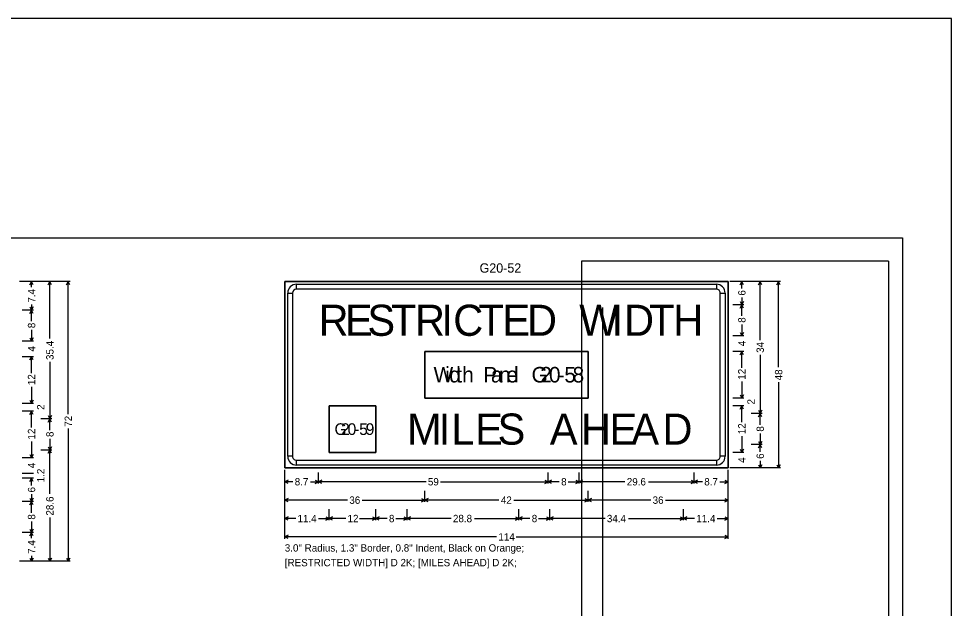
# Model space of a CAD drawing. Extents: x -1403959 to 81668, y -1400582 to 11018.
# Drawn here: x -1402613 to -1400615, y -1399262 to -1397998 of the extents above; entities that cross this region are included whole.
import ezdxf

# ---------------------------------------------------------------- set-up
doc = ezdxf.new("R2010")
doc.units = 0
for name, color, linetype in [('tdCiInt', 7, 'Continuous'), ('tdCiIntRampCL', 7, 'Continuous'), ('tdCiPriRamp', 7, 'Continuous'), ('tdCiPriRampCL', 7, 'Continuous'), ('tdRailNorfolk_South', 7, 'Continuous'), ('trf_Sign_Details_Border', 7, 'Continuous'), ('trf_Sign_Details_Dimensions', 7, 'Continuous')]:
    doc.layers.add(name, color=color, linetype=linetype)

msp = doc.modelspace()

# ---------------------------------------------------------------- linework, layer by layer
at = {"layer": 'tdCiInt'}
for p, q in [((-1402018.1, -1398577.7), (-1402018.1, -1398567.3)), ((-1401118.1, -1398567.3), (-1401118.1, -1398577.7)), ((-1402036.8, -1398586), (-1402026.4, -1398586)), ((-1401109.7, -1398586), (-1401099.3, -1398586)), ((-1401393.1, -1398711), (-1401743.1, -1398711)), ((-1401743.1, -1398711), (-1401743.1, -1398811)), ((-1401393.1, -1398811), (-1401393.1, -1398711)), ((-1401743.1, -1398811), (-1401393.1, -1398811)), ((-1401847.7, -1398827.7), (-1401947.7, -1398827.7)), ((-1401947.7, -1398827.7), (-1401947.7, -1398927.7)), ((-1401847.7, -1398927.7), (-1401847.7, -1398827.7)), ((-1402026.4, -1398936), (-1402036.8, -1398936)), ((-1401947.7, -1398927.7), (-1401847.7, -1398927.7)), ((-1401099.3, -1398936), (-1401109.7, -1398936)), ((-1402018.1, -1398954.8), (-1402018.1, -1398944.4)), ((-1401118.1, -1398944.4), (-1401118.1, -1398954.8))]:
    msp.add_line(p, q, dxfattribs=at)
for points in [[(-1402043.1, -1398961), (-1401093.1, -1398961), (-1401093.1, -1398561), (-1402043.1, -1398561), (-1402043.1, -1398961)], [(-1401118.1, -1398577.7), (-1402018.1, -1398577.7), (-1402018.1, -1398567.3), (-1401118.1, -1398567.3), (-1401118.1, -1398577.7)], [(-1402026.4, -1398586), (-1402026.4, -1398936), (-1402036.8, -1398936), (-1402036.8, -1398586), (-1402026.4, -1398586)], [(-1401109.7, -1398936), (-1401109.7, -1398586), (-1401099.3, -1398586), (-1401099.3, -1398936), (-1401109.7, -1398936)], [(-1402018.1, -1398944.4), (-1401118.1, -1398944.4), (-1401118.1, -1398954.8), (-1402018.1, -1398954.8), (-1402018.1, -1398944.4)]]:
    msp.add_lwpolyline(points, close=True, dxfattribs=at)
for centre, radius, start, end in [((-1402018.1, -1398586), 18.8, 90.0002, 179.9998), ((-1402018.1, -1398586), 8.33, 90.0002, 179.9998), ((-1401118.1, -1398586), 18.8, 0, 90.0002), ((-1401118.1, -1398586), 8.33, 0, 90.0002), ((-1402018.1, -1398936), 18.8, 179.9998, 270.0001), ((-1402018.1, -1398936), 8.33, 179.9998, 270.0001), ((-1401118.1, -1398936), 18.8, 270.0001, 0.0003), ((-1401118.1, -1398936), 8.33, 270.0001, 0.0003)]:
    msp.add_arc(centre, radius, start, end, dxfattribs=at)
at = {"layer": 'tdCiIntRampCL'}
msp.add_lwpolyline([(-1403958.5, -1400581.8), (-1400614.5, -1400581.8), (-1400614.5, -1397997.8), (-1403958.5, -1397997.8)], close=True, dxfattribs=at)
at = {"layer": 'tdCiPriRamp'}
msp.add_lwpolyline([(-1403854, -1398467.3), (-1400719, -1398467.3), (-1400719, -1400477.3), (-1403854, -1400477.3)], close=True, dxfattribs=at)
at = {"layer": 'tdCiPriRampCL'}
for p, q in [((-1401407.1, -1398517.3), (-1401407.1, -1399987.3)), ((-1400749, -1398517.3), (-1401407.1, -1398517.3)), ((-1400749, -1398517.3), (-1400749, -1399987.3)), ((-1401362.1, -1398617.3), (-1401362.1, -1399608.8))]:
    msp.add_line(p, q, dxfattribs=at)
at = {"layer": 'trf_Sign_Details_Border'}
for points in [[(-1402043.1, -1398561), (-1401093.1, -1398561), (-1401093.1, -1398961), (-1402043.1, -1398961)], [(-1401743.1, -1398711), (-1401393.1, -1398711), (-1401393.1, -1398811), (-1401743.1, -1398811)], [(-1401947.7, -1398827.7), (-1401847.7, -1398827.7), (-1401847.7, -1398927.7), (-1401947.7, -1398927.7)]]:
    msp.add_lwpolyline(points, close=True, dxfattribs=at)
at = {"layer": 'trf_Sign_Details_Dimensions'}
for p, q in [((-1402503.2, -1398561), (-1402611.5, -1398561)), ((-1402582, -1398561), (-1402605.6, -1398561)), ((-1402589.4, -1398568.1), (-1402585.9, -1398561)), ((-1402585.9, -1398573.1), (-1402585.9, -1398561)), ((-1402582.4, -1398568.1), (-1402585.9, -1398561)), ((-1402542.6, -1398561), (-1402566.2, -1398561)), ((-1402550.1, -1398568.1), (-1402546.5, -1398561)), ((-1402546.5, -1398683.4), (-1402546.5, -1398561)), ((-1402543, -1398568.1), (-1402546.5, -1398561)), ((-1402510.7, -1398568.1), (-1402507.2, -1398561)), ((-1402507.2, -1398845.5), (-1402507.2, -1398561)), ((-1402503.6, -1398568.1), (-1402507.2, -1398561)), ((-1400980.9, -1398561), (-1401089.1, -1398561)), ((-1401059.6, -1398561), (-1401083.2, -1398561)), ((-1401067.1, -1398568.1), (-1401063.5, -1398561)), ((-1401063.5, -1398576.6), (-1401063.5, -1398561)), ((-1401060, -1398568.1), (-1401063.5, -1398561)), ((-1401020.2, -1398561), (-1401043.9, -1398561)), ((-1401027.7, -1398568.1), (-1401024.2, -1398561)), ((-1401024.2, -1398687.2), (-1401024.2, -1398561)), ((-1401020.7, -1398568.1), (-1401024.2, -1398561)), ((-1400988.3, -1398568.1), (-1400984.8, -1398561)), ((-1400984.8, -1398745), (-1400984.8, -1398561)), ((-1400981.3, -1398568.1), (-1400984.8, -1398561)), ((-1401067.1, -1398604), (-1401063.5, -1398611)), ((-1401063.5, -1398595.5), (-1401063.5, -1398611)), ((-1401060, -1398604), (-1401063.5, -1398611)), ((-1402582, -1398622.5), (-1402605.6, -1398622.5)), ((-1402589.4, -1398615.4), (-1402585.9, -1398622.5)), ((-1402589.4, -1398629.5), (-1402585.9, -1398622.5)), ((-1402585.9, -1398610.4), (-1402585.9, -1398622.5)), ((-1402582.4, -1398615.4), (-1402585.9, -1398622.5)), ((-1402585.9, -1398646.4), (-1402585.9, -1398622.5)), ((-1402582.4, -1398629.5), (-1402585.9, -1398622.5)), ((-1401059.6, -1398611), (-1401083.2, -1398611)), ((-1401067.1, -1398618.1), (-1401063.5, -1398611)), ((-1401063.5, -1398635), (-1401063.5, -1398611)), ((-1401060, -1398618.1), (-1401063.5, -1398611)), ((-1401063.5, -1398653.7), (-1401063.5, -1398677.7)), ((-1402589.4, -1398682.1), (-1402585.9, -1398689.1)), ((-1402585.9, -1398665.2), (-1402585.9, -1398689.1)), ((-1402582.4, -1398682.1), (-1402585.9, -1398689.1)), ((-1401059.6, -1398677.7), (-1401083.2, -1398677.7)), ((-1401067.1, -1398670.6), (-1401063.5, -1398677.7)), ((-1401060, -1398670.6), (-1401063.5, -1398677.7)), ((-1402582, -1398689.1), (-1402605.6, -1398689.1)), ((-1402582, -1398722.5), (-1402605.6, -1398722.5)), ((-1402589.4, -1398729.5), (-1402585.9, -1398722.5)), ((-1402585.9, -1398757.7), (-1402585.9, -1398722.5)), ((-1402582.4, -1398729.5), (-1402585.9, -1398722.5)), ((-1401059.6, -1398711), (-1401083.2, -1398711)), ((-1401067.1, -1398718.1), (-1401063.5, -1398711)), ((-1401063.5, -1398746.2), (-1401063.5, -1398711)), ((-1401060, -1398718.1), (-1401063.5, -1398711)), ((-1401024.2, -1398718.2), (-1401024.2, -1398844.4)), ((-1402546.5, -1398733.4), (-1402546.5, -1398855.8)), ((-1401063.5, -1398775.8), (-1401063.5, -1398811)), ((-1400984.8, -1398777), (-1400984.8, -1398961)), ((-1402585.9, -1398787.3), (-1402585.9, -1398822.5)), ((-1401067.1, -1398804), (-1401063.5, -1398811)), ((-1401060, -1398804), (-1401063.5, -1398811)), ((-1402582, -1398822.5), (-1402605.6, -1398822.5)), ((-1402589.4, -1398815.4), (-1402585.9, -1398822.5)), ((-1402582.4, -1398815.4), (-1402585.9, -1398822.5)), ((-1401059.6, -1398811), (-1401083.2, -1398811)), ((-1402582, -1398839.1), (-1402605.6, -1398839.1)), ((-1402589.4, -1398846.2), (-1402585.9, -1398839.1)), ((-1402585.9, -1398874.3), (-1402585.9, -1398839.1)), ((-1402582.4, -1398846.2), (-1402585.9, -1398839.1)), ((-1401059.6, -1398827.7), (-1401083.2, -1398827.7)), ((-1401067.1, -1398834.7), (-1401063.5, -1398827.7)), ((-1401063.5, -1398862.9), (-1401063.5, -1398827.7)), ((-1401060, -1398834.7), (-1401063.5, -1398827.7)), ((-1401027.7, -1398837.3), (-1401024.2, -1398844.4)), ((-1401020.7, -1398837.3), (-1401024.2, -1398844.4)), ((-1402542.6, -1398855.8), (-1402566.2, -1398855.8)), ((-1402550.1, -1398848.8), (-1402546.5, -1398855.8)), ((-1402550.1, -1398862.9), (-1402546.5, -1398855.8)), ((-1402543, -1398848.8), (-1402546.5, -1398855.8)), ((-1402546.5, -1398879.8), (-1402546.5, -1398855.8)), ((-1402543, -1398862.9), (-1402546.5, -1398855.8)), ((-1401020.2, -1398844.4), (-1401043.9, -1398844.4)), ((-1401027.7, -1398851.4), (-1401024.2, -1398844.4)), ((-1401024.2, -1398868.3), (-1401024.2, -1398844.4)), ((-1401020.7, -1398851.4), (-1401024.2, -1398844.4)), ((-1402507.2, -1398876.5), (-1402507.2, -1399161)), ((-1402585.9, -1398904), (-1402585.9, -1398939.1)), ((-1402546.5, -1398898.5), (-1402546.5, -1398922.5)), ((-1401063.5, -1398892.5), (-1401063.5, -1398927.7)), ((-1401027.7, -1398904), (-1401024.2, -1398911)), ((-1401024.2, -1398887.1), (-1401024.2, -1398911)), ((-1401020.7, -1398904), (-1401024.2, -1398911)), ((-1402542.6, -1398922.5), (-1402566.2, -1398922.5)), ((-1402542.6, -1398922.5), (-1402566.2, -1398922.5)), ((-1402550.1, -1398915.4), (-1402546.5, -1398922.5)), ((-1402550.1, -1398929.5), (-1402546.5, -1398922.5)), ((-1402543, -1398915.4), (-1402546.5, -1398922.5)), ((-1402546.5, -1399016.4), (-1402546.5, -1398922.5)), ((-1402543, -1398929.5), (-1402546.5, -1398922.5)), ((-1401067.1, -1398920.6), (-1401063.5, -1398927.7)), ((-1401060, -1398920.6), (-1401063.5, -1398927.7)), ((-1401020.2, -1398911), (-1401043.9, -1398911)), ((-1401020.2, -1398911), (-1401043.9, -1398911)), ((-1401027.7, -1398918.1), (-1401024.2, -1398911)), ((-1401024.2, -1398926.6), (-1401024.2, -1398911)), ((-1401020.7, -1398918.1), (-1401024.2, -1398911)), ((-1402582, -1398939.1), (-1402605.6, -1398939.1)), ((-1402589.4, -1398932.1), (-1402585.9, -1398939.1)), ((-1402582.4, -1398932.1), (-1402585.9, -1398939.1)), ((-1401059.6, -1398927.7), (-1401083.2, -1398927.7)), ((-1401059.6, -1398927.7), (-1401083.2, -1398927.7)), ((-1400980.9, -1398961), (-1401089.1, -1398961)), ((-1401059.6, -1398961), (-1401083.2, -1398961)), ((-1401020.2, -1398961), (-1401043.9, -1398961)), ((-1401027.7, -1398954), (-1401024.2, -1398961)), ((-1401024.2, -1398945.5), (-1401024.2, -1398961)), ((-1401020.7, -1398954), (-1401024.2, -1398961)), ((-1400988.3, -1398954), (-1400984.8, -1398961)), ((-1400981.3, -1398954), (-1400984.8, -1398961)), ((-1402582, -1398972.5), (-1402605.6, -1398972.5)), ((-1402582, -1398982.9), (-1402605.6, -1398982.9)), ((-1402589.4, -1398989.9), (-1402585.9, -1398982.9)), ((-1402585.9, -1398998.4), (-1402585.9, -1398982.9)), ((-1402582.4, -1398989.9), (-1402585.9, -1398982.9)), ((-1402043.1, -1399112.6), (-1402043.1, -1398965)), ((-1402043.1, -1398994.5), (-1402043.1, -1398970.9)), ((-1401970.7, -1398994.5), (-1401970.7, -1398970.9)), ((-1401478.7, -1398994.5), (-1401478.7, -1398970.9)), ((-1401412.1, -1398994.5), (-1401412.1, -1398970.9)), ((-1401165.4, -1398994.5), (-1401165.4, -1398970.9)), ((-1401165.4, -1398994.5), (-1401165.4, -1398970.9)), ((-1401093.1, -1399112.6), (-1401093.1, -1398965)), ((-1401093.1, -1398994.5), (-1401093.1, -1398970.9)), ((-1402036, -1398987), (-1402043.1, -1398990.5)), ((-1402025.7, -1398990.5), (-1402043.1, -1398990.5)), ((-1402036, -1398994.1), (-1402043.1, -1398990.5)), ((-1401988.1, -1398990.5), (-1401970.7, -1398990.5)), ((-1401977.8, -1398987), (-1401970.7, -1398990.5)), ((-1401977.8, -1398994.1), (-1401970.7, -1398990.5)), ((-1401963.7, -1398987), (-1401970.7, -1398990.5)), ((-1401740.4, -1398990.5), (-1401970.7, -1398990.5)), ((-1401963.7, -1398994.1), (-1401970.7, -1398990.5)), ((-1401709.1, -1398990.5), (-1401478.7, -1398990.5)), ((-1401485.8, -1398987), (-1401478.7, -1398990.5)), ((-1401485.8, -1398994.1), (-1401478.7, -1398990.5)), ((-1401471.7, -1398987), (-1401478.7, -1398990.5)), ((-1401454.8, -1398990.5), (-1401478.7, -1398990.5)), ((-1401471.7, -1398994.1), (-1401478.7, -1398990.5)), ((-1401436, -1398990.5), (-1401412.1, -1398990.5)), ((-1401419.1, -1398987), (-1401412.1, -1398990.5)), ((-1401419.1, -1398994.1), (-1401412.1, -1398990.5)), ((-1401405, -1398987), (-1401412.1, -1398990.5)), ((-1401314.1, -1398990.5), (-1401412.1, -1398990.5)), ((-1401405, -1398994.1), (-1401412.1, -1398990.5)), ((-1401263.4, -1398990.5), (-1401165.4, -1398990.5)), ((-1401172.4, -1398987), (-1401165.4, -1398990.5)), ((-1401172.4, -1398994.1), (-1401165.4, -1398990.5)), ((-1401158.4, -1398987), (-1401165.4, -1398990.5)), ((-1401148.1, -1398990.5), (-1401165.4, -1398990.5)), ((-1401158.4, -1398994.1), (-1401165.4, -1398990.5)), ((-1401110.4, -1398990.5), (-1401093.1, -1398990.5)), ((-1401100.1, -1398987), (-1401093.1, -1398990.5)), ((-1401100.1, -1398994.1), (-1401093.1, -1398990.5)), ((-1402585.9, -1399017.4), (-1402585.9, -1399032.9)), ((-1402043.1, -1399033.9), (-1402043.1, -1399010.2)), ((-1401743.1, -1399033.9), (-1401743.1, -1399010.2)), ((-1401393.1, -1399033.9), (-1401393.1, -1399010.2)), ((-1401393.1, -1399033.9), (-1401393.1, -1399010.2)), ((-1401093.1, -1399033.9), (-1401093.1, -1399010.2)), ((-1402582, -1399032.9), (-1402605.6, -1399032.9)), ((-1402589.4, -1399025.9), (-1402585.9, -1399032.9)), ((-1402589.4, -1399039.9), (-1402585.9, -1399032.9)), ((-1402582.4, -1399025.9), (-1402585.9, -1399032.9)), ((-1402585.9, -1399056.9), (-1402585.9, -1399032.9)), ((-1402582.4, -1399039.9), (-1402585.9, -1399032.9)), ((-1402036, -1399026.4), (-1402043.1, -1399029.9)), ((-1401908.8, -1399029.9), (-1402043.1, -1399029.9)), ((-1402036, -1399033.4), (-1402043.1, -1399029.9)), ((-1401877.4, -1399029.9), (-1401743.1, -1399029.9)), ((-1401750.1, -1399026.4), (-1401743.1, -1399029.9)), ((-1401750.1, -1399033.4), (-1401743.1, -1399029.9)), ((-1401736, -1399026.4), (-1401743.1, -1399029.9)), ((-1401584, -1399029.9), (-1401743.1, -1399029.9)), ((-1401736, -1399033.4), (-1401743.1, -1399029.9)), ((-1401552.2, -1399029.9), (-1401393.1, -1399029.9)), ((-1401400.1, -1399026.4), (-1401393.1, -1399029.9)), ((-1401400.1, -1399033.4), (-1401393.1, -1399029.9)), ((-1401386, -1399026.4), (-1401393.1, -1399029.9)), ((-1401258.8, -1399029.9), (-1401393.1, -1399029.9)), ((-1401386, -1399033.4), (-1401393.1, -1399029.9)), ((-1401227.4, -1399029.9), (-1401093.1, -1399029.9)), ((-1401100.1, -1399026.4), (-1401093.1, -1399029.9)), ((-1401100.1, -1399033.4), (-1401093.1, -1399029.9)), ((-1402043.1, -1399073.2), (-1402043.1, -1399049.6)), ((-1401947.7, -1399073.2), (-1401947.7, -1399049.6)), ((-1401847.7, -1399073.2), (-1401847.7, -1399049.6)), ((-1401781.1, -1399073.2), (-1401781.1, -1399049.6)), ((-1401541.7, -1399073.2), (-1401541.7, -1399049.6)), ((-1401475.1, -1399073.2), (-1401475.1, -1399049.6)), ((-1401188.4, -1399073.2), (-1401188.4, -1399049.6)), ((-1401188.4, -1399073.2), (-1401188.4, -1399049.6)), ((-1401093.1, -1399073.2), (-1401093.1, -1399049.6)), ((-1402585.9, -1399075.6), (-1402585.9, -1399099.6)), ((-1402546.5, -1399067.1), (-1402546.5, -1399161)), ((-1402036, -1399065.8), (-1402043.1, -1399069.3)), ((-1402019.7, -1399069.3), (-1402043.1, -1399069.3)), ((-1402036, -1399072.8), (-1402043.1, -1399069.3)), ((-1401971.1, -1399069.3), (-1401947.7, -1399069.3)), ((-1401954.8, -1399065.8), (-1401947.7, -1399069.3)), ((-1401954.8, -1399072.8), (-1401947.7, -1399069.3)), ((-1401940.7, -1399065.8), (-1401947.7, -1399069.3)), ((-1401912.6, -1399069.3), (-1401947.7, -1399069.3)), ((-1401940.7, -1399072.8), (-1401947.7, -1399069.3)), ((-1401882.9, -1399069.3), (-1401847.7, -1399069.3)), ((-1401854.8, -1399065.8), (-1401847.7, -1399069.3)), ((-1401854.8, -1399072.8), (-1401847.7, -1399069.3)), ((-1401840.7, -1399065.8), (-1401847.7, -1399069.3)), ((-1401823.8, -1399069.3), (-1401847.7, -1399069.3)), ((-1401840.7, -1399072.8), (-1401847.7, -1399069.3)), ((-1401805, -1399069.3), (-1401781.1, -1399069.3)), ((-1401788.1, -1399065.8), (-1401781.1, -1399069.3)), ((-1401788.1, -1399072.8), (-1401781.1, -1399069.3)), ((-1401774, -1399065.8), (-1401781.1, -1399069.3)), ((-1401686.7, -1399069.3), (-1401781.1, -1399069.3)), ((-1401774, -1399072.8), (-1401781.1, -1399069.3)), ((-1401636.2, -1399069.3), (-1401541.7, -1399069.3)), ((-1401548.8, -1399065.8), (-1401541.7, -1399069.3)), ((-1401548.8, -1399072.8), (-1401541.7, -1399069.3)), ((-1401534.7, -1399065.8), (-1401541.7, -1399069.3)), ((-1401517.8, -1399069.3), (-1401541.7, -1399069.3)), ((-1401534.7, -1399072.8), (-1401541.7, -1399069.3)), ((-1401499, -1399069.3), (-1401475.1, -1399069.3)), ((-1401482.1, -1399065.8), (-1401475.1, -1399069.3)), ((-1401482.1, -1399072.8), (-1401475.1, -1399069.3)), ((-1401468, -1399065.8), (-1401475.1, -1399069.3)), ((-1401356.7, -1399069.3), (-1401475.1, -1399069.3)), ((-1401468, -1399072.8), (-1401475.1, -1399069.3)), ((-1401306.7, -1399069.3), (-1401188.4, -1399069.3)), ((-1401195.4, -1399065.8), (-1401188.4, -1399069.3)), ((-1401195.4, -1399072.8), (-1401188.4, -1399069.3)), ((-1401181.4, -1399065.8), (-1401188.4, -1399069.3)), ((-1401165, -1399069.3), (-1401188.4, -1399069.3)), ((-1401181.4, -1399072.8), (-1401188.4, -1399069.3)), ((-1401116.4, -1399069.3), (-1401093.1, -1399069.3)), ((-1401100.1, -1399065.8), (-1401093.1, -1399069.3)), ((-1401100.1, -1399072.8), (-1401093.1, -1399069.3)), ((-1402582, -1399099.6), (-1402605.6, -1399099.6)), ((-1402582, -1399099.6), (-1402605.6, -1399099.6)), ((-1402589.4, -1399092.5), (-1402585.9, -1399099.6)), ((-1402589.4, -1399106.6), (-1402585.9, -1399099.6)), ((-1402582.4, -1399092.5), (-1402585.9, -1399099.6)), ((-1402585.9, -1399111.6), (-1402585.9, -1399099.6)), ((-1402582.4, -1399106.6), (-1402585.9, -1399099.6)), ((-1402036, -1399105.1), (-1402043.1, -1399108.7)), ((-1401589.2, -1399108.7), (-1402043.1, -1399108.7)), ((-1402036, -1399112.2), (-1402043.1, -1399108.7)), ((-1401546.9, -1399108.7), (-1401093.1, -1399108.7)), ((-1401100.1, -1399105.1), (-1401093.1, -1399108.7)), ((-1401100.1, -1399112.2), (-1401093.1, -1399108.7)), ((-1402503.2, -1399161), (-1402611.5, -1399161)), ((-1402582, -1399161), (-1402605.6, -1399161)), ((-1402589.4, -1399154), (-1402585.9, -1399161)), ((-1402585.9, -1399149), (-1402585.9, -1399161)), ((-1402582.4, -1399154), (-1402585.9, -1399161)), ((-1402542.6, -1399161), (-1402566.2, -1399161)), ((-1402550.1, -1399154), (-1402546.5, -1399161)), ((-1402543, -1399154), (-1402546.5, -1399161)), ((-1402510.7, -1399154), (-1402507.2, -1399161)), ((-1402503.6, -1399154), (-1402507.2, -1399161))]:
    msp.add_line(p, q, dxfattribs=at)

# ---------------------------------------------------------------- texts
at = {"layer": 'tdCiInt'}
for s, height, p in [('R', 66.7, (-1401970.7, -1398677.7)), ('E', 66.7, (-1401914.1, -1398677.7)), ('S', 66.7, (-1401866.1, -1398677.7)), ('T', 66.7, (-1401815.4, -1398677.7)), ('R', 66.7, (-1401764.1, -1398677.7)), ('I', 66.7, (-1401707.4, -1398677.7)), ('C', 66.7, (-1401682.1, -1398677.7)), ('T', 66.7, (-1401628.1, -1398677.7)), ('E', 66.7, (-1401576.7, -1398677.7)), ('D', 66.7, (-1401524.1, -1398677.7)), ('W', 66.7, (-1401412.1, -1398677.7)), ('I', 66.7, (-1401342.7, -1398677.7)), ('D', 66.7, (-1401316.1, -1398677.7)), ('T', 66.7, (-1401262.1, -1398677.7)), ('H', 66.7, (-1401210.7, -1398677.7)), ('i', 33.3, (-1401699.2, -1398777.7)), ('d', 33.3, (-1401690.6, -1398777.7)), ('h', 33.3, (-1401662.9, -1398777.7)), ('l', 33.3, (-1401551.9, -1398777.7)), ('G', 33.3, (-1401514.2, -1398777.7)), ('2', 33.3, (-1401495.6, -1398777.7)), ('0', 33.3, (-1401476.9, -1398777.7)), ('8', 33.3, (-1401426.2, -1398777.7)), ('W', 33.3, (-1401724.2, -1398777.7)), ('t', 33.3, (-1401675.6, -1398777.7)), ('P', 33.3, (-1401617.6, -1398777.7)), ('a', 33.3, (-1401601.2, -1398777.7)), ('n', 33.3, (-1401583.9, -1398777.7)), ('e', 33.3, (-1401567.9, -1398777.7)), ('-', 33.3, (-1401457.9, -1398777.7)), ('5', 33.3, (-1401443.9, -1398777.7)), ('S', 66.7, (-1401587.1, -1398911)), ('M', 66.7, (-1401781.1, -1398911)), ('I', 66.7, (-1401713.1, -1398911)), ('L', 66.7, (-1401686.4, -1398911)), ('E', 66.7, (-1401635.1, -1398911)), ('A', 66.7, (-1401475.1, -1398911)), ('H', 66.7, (-1401408.4, -1398911)), ('E', 66.7, (-1401347.1, -1398911)), ('A', 66.7, (-1401300.4, -1398911)), ('D', 66.7, (-1401233.7, -1398911)), ('G', 25, (-1401936.5, -1398890.2)), ('2', 25, (-1401922.5, -1398890.2)), ('0', 25, (-1401908.5, -1398890.2)), ('-', 25, (-1401894.2, -1398890.2)), ('5', 25, (-1401883.7, -1398890.2)), ('9', 25, (-1401869.7, -1398890.2))]:
    msp.add_text(s, height=height, dxfattribs=at).set_placement(p)
at = {"layer": 'tdRailNorfolk_South'}
msp.add_text('G20-52', height=20, dxfattribs=at).set_placement((-1401625.6, -1398542.3))
at = {"layer": 'trf_Sign_Details_Dimensions'}
for s, height, p in [('7.4', 15.75, (-1402578, -1398606.5)), ('6', 15.7, (-1401055.7, -1398591.5)), ('8', 15.7, (-1401055.7, -1398649.8)), ('8', 15.7, (-1402578, -1398661.3)), ('4', 15.7, (-1402578, -1398711.5)), ('35.4', 15.75, (-1402538.7, -1398729.5)), ('4', 15.7, (-1401055.7, -1398700)), ('34', 15.75, (-1401016.3, -1398714.3)), ('12', 15.75, (-1402578, -1398783.4)), ('12', 15.75, (-1401055.7, -1398771.9)), ('48', 15.75, (-1400976.9, -1398773.1)), ('2', 15.7, (-1401036, -1398824.8)), ('2', 15.7, (-1402558.3, -1398836.3)), ('72', 15.75, (-1402499.3, -1398872.6)), ('12', 15.75, (-1402578, -1398900)), ('8', 15.7, (-1402538.7, -1398894.6)), ('12', 15.75, (-1401055.7, -1398888.6)), ('8', 15.7, (-1401016.3, -1398883.1)), ('4', 15.7, (-1401055.7, -1398950)), ('6', 15.7, (-1401016.3, -1398941.5)), ('4', 15.7, (-1402578, -1398961.5)), ('1.2', 15.75, (-1402558.3, -1398991.7)), ('6', 15.7, (-1402578, -1399013.4)), ('28.6', 15.75, (-1402538.7, -1399063.1)), ('8', 15.7, (-1402578, -1399071.7)), ('7.4', 15.75, (-1402578, -1399145.1))]:
    msp.add_text(s, height=height, rotation=90.0002, dxfattribs=at).set_placement(p)
for s, height, p in [('8.7', 15.75, (-1402021.8, -1398998.4)), ('59', 15.75, (-1401736.4, -1398998.4)), ('8', 15.7, (-1401450.8, -1398998.4)), ('29.6', 15.75, (-1401310.1, -1398998.4)), ('8.7', 15.75, (-1401144.1, -1398998.4)), ('36', 15.75, (-1401904.8, -1399037.8)), ('42', 15.75, (-1401580, -1399037.8)), ('36', 15.75, (-1401254.8, -1399037.8)), ('11.4', 15.75, (-1402015.8, -1399077.2)), ('12', 15.75, (-1401908.6, -1399077.2)), ('8', 15.7, (-1401819.8, -1399077.2)), ('28.8', 15.75, (-1401682.7, -1399077.2)), ('8', 15.7, (-1401513.8, -1399077.2)), ('34.4', 15.75, (-1401352.8, -1399077.2)), ('11.4', 15.75, (-1401161.1, -1399077.2)), ('114', 15.75, (-1401585.3, -1399116.5)), ('3.0" Radius, 1.3" Border, 0.8" Indent, Black on Orange; ', 15.748, (-1402043.1, -1399140.2)), ('[RESTRICTED WIDTH] D 2K; [MILES AHEAD] D 2K; ', 15.748, (-1402043.1, -1399171.7))]:
    msp.add_text(s, height=height, dxfattribs=at).set_placement(p)

doc.saveas('drawing.dxf')
